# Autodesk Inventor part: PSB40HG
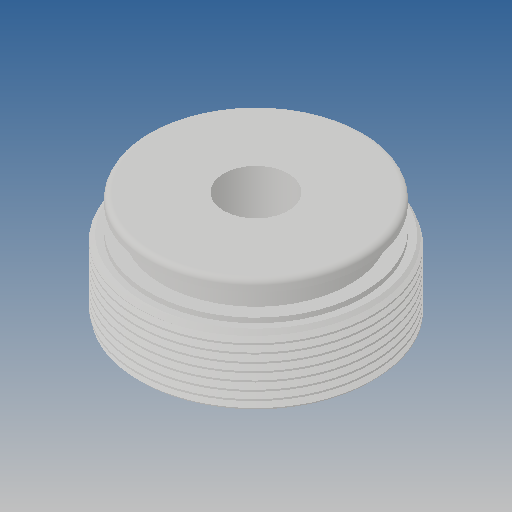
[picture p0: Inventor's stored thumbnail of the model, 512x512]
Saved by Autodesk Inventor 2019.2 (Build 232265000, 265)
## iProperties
Created: 2013-10
Part Number: PSB40HG
Material: Ogólny
Document SubType Name: Modeling
Designer: CADENGINEERING4
Density: 1 g/cm^3
Appearance: Domyślna
Author: CADENGINEERING4
Revision Number: ÈÎºÎ
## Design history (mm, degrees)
feature "ÇÐ³ý-É¨Ãè1"
node "Bryła1"
